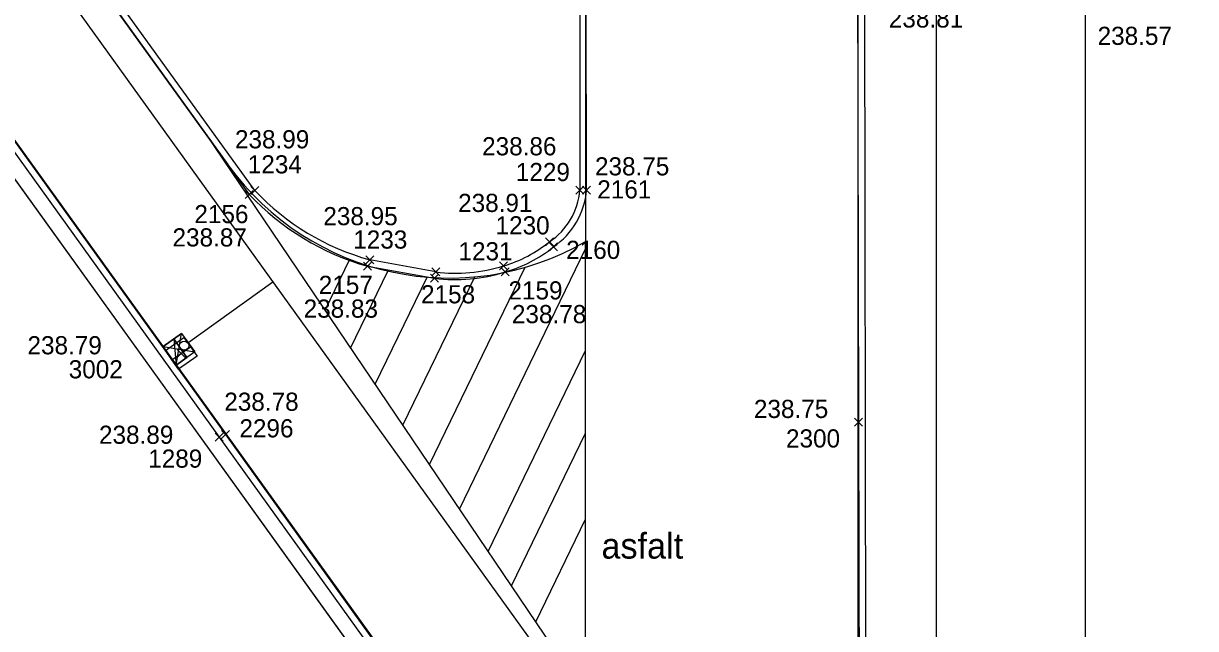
# Model space of a CAD drawing. Extents: x -264222 to -263676, y -1242344 to -1242060.
# Drawn here: x -264143.94 to -264118.14, y -1242285.58 to -1242272.25 of the extents above; entities that cross this region are included whole.
import ezdxf

# ---------------------------------------------------------------- set-up
doc = ezdxf.new("R2010")
doc.units = 0
for name, color, linetype in [('BODY_CISLO', 7, 'Continuous'), ('BODY_SYMBOL', 7, 'Continuous'), ('BODY_VYSKA', 7, 'Continuous'), ('BODY_VYSKY_UV', 7, 'Continuous'), ('KOORDINACNA_SITUACIA_DSP', 7, 'Continuous'), ('POPIS', 7, 'Continuous'), ('PROJEKT_DRS_OBRUBNIKY_KOMUNIKACIE', 7, 'Continuous'), ('PROJEKT_DRS_TDZ_VODOROVNE', 7, 'Continuous'), ('PROJEKT_DRS_UV_STAVBY', 7, 'Continuous'), ('SO_20-3_OBRUBNIKY_DOLNA_HRANA', 7, 'Continuous'), ('SO_20-3_OBRUBNIKY_HORNA_HRANA', 7, 'Continuous'), ('ULICNA_VPUST_POKLOP', 7, 'Continuous')]:
    doc.layers.add(name, color=color, linetype=linetype)

msp = doc.modelspace()

# ---------------------------------------------------------------- linework, layer by layer
at = {"layer": 'BODY_SYMBOL'}
for p, q in [((-264139.06, -1242276.105), (-264138.884, -1242275.929)), ((-264138.884, -1242276.105), (-264139.06, -1242275.929)), ((-264138.939, -1242276.021), (-264138.763, -1242275.845)), ((-264138.763, -1242276.021), (-264138.939, -1242275.845)), ((-264131.781, -1242276.013), (-264131.605, -1242275.837)), ((-264131.605, -1242276.013), (-264131.781, -1242275.837)), ((-264131.636, -1242276.013), (-264131.46, -1242275.837)), ((-264131.46, -1242276.013), (-264131.636, -1242275.837)), ((-264132.453, -1242277.149), (-264132.277, -1242276.973)), ((-264132.277, -1242277.149), (-264132.453, -1242276.973)), ((-264132.363, -1242277.261), (-264132.187, -1242277.085)), ((-264132.187, -1242277.261), (-264132.363, -1242277.085)), ((-264136.408, -1242277.546), (-264136.232, -1242277.37)), ((-264136.232, -1242277.546), (-264136.408, -1242277.37)), ((-264136.454, -1242277.688), (-264136.278, -1242277.512)), ((-264136.278, -1242277.688), (-264136.454, -1242277.512)), ((-264133.463, -1242277.682), (-264133.287, -1242277.506)), ((-264133.287, -1242277.682), (-264133.463, -1242277.506)), ((-264134.979, -1242277.951), (-264134.803, -1242277.775)), ((-264134.803, -1242277.951), (-264134.979, -1242277.775)), ((-264134.953, -1242277.814), (-264134.777, -1242277.638)), ((-264134.777, -1242277.814), (-264134.953, -1242277.638)), ((-264133.427, -1242277.814), (-264133.251, -1242277.638)), ((-264133.251, -1242277.814), (-264133.427, -1242277.638)), ((-264140.556, -1242279.607), (-264140.38, -1242279.431)), ((-264140.38, -1242279.607), (-264140.556, -1242279.431)), ((-264125.649, -1242281.122), (-264125.473, -1242280.946)), ((-264125.473, -1242281.122), (-264125.649, -1242280.946)), ((-264139.584, -1242281.393), (-264139.408, -1242281.217)), ((-264139.408, -1242281.393), (-264139.584, -1242281.217)), ((-264139.719, -1242281.449), (-264139.543, -1242281.273)), ((-264139.543, -1242281.449), (-264139.719, -1242281.273))]:
    msp.add_line(p, q, dxfattribs=at)
at = {"layer": 'KOORDINACNA_SITUACIA_DSP'}
for p, q in [((-264204.694, -1242191.482), (-264122.859, -1242305.266)), ((-264204.078, -1242191.482), (-264122.243, -1242305.266)), ((-264123.854, -1242237.976), (-264123.854, -1242297.736)), ((-264153.916, -1242255.234), (-264139.439, -1242275.363)), ((-264152.757, -1242258.05), (-264124.146, -1242297.83)), ((-264152.757, -1242258.05), (-264124.146, -1242297.83)), ((-264131.568, -1242270.982), (-264131.568, -1242277.056)), ((-264125.568, -1242287.467), (-264125.568, -1242270.982)), ((-264140.324, -1242279.287), (-264138.451, -1242277.94)), ((-264140.868, -1242279.37), (-264140.632, -1242279.201)), ((-264140.576, -1242279.776), (-264140.868, -1242279.37)), ((-264140.632, -1242279.201), (-264140.341, -1242279.607)), ((-264140.632, -1242279.201), (-264140.576, -1242279.776)), ((-264140.632, -1242279.201), (-264140.576, -1242279.776)), ((-264140.341, -1242279.607), (-264140.632, -1242279.201)), ((-264140.341, -1242279.607), (-264140.576, -1242279.776)), ((-264140.576, -1242279.776), (-264140.341, -1242279.607))]:
    msp.add_line(p, q, dxfattribs=at)
for points in [[(-264204.694, -1242191.482), (-264137.78, -1242284.52), (-264125.581, -1242301.482)], [(-264120.568, -1242296.035), (-264120.568, -1242271.189), (-264120.568, -1242271.189)]]:
    msp.add_lwpolyline(points, dxfattribs=at)
msp.add_circle((-264140.403, -1242279.349), 0.1, dxfattribs=at)
msp.add_arc((-264134.568, -1242271.86), 6, 215.724, 300, dxfattribs=at)
at = {"layer": 'PROJEKT_DRS_OBRUBNIKY_KOMUNIKACIE'}
for p, q in [((-264204.694, -1242191.482), (-264115.871, -1242314.982)), ((-264204.078, -1242191.482), (-264119.571, -1242308.982)), ((-264153.916, -1242255.234), (-264139.439, -1242275.363)), ((-264131.568, -1242270.982), (-264131.568, -1242277.056)), ((-264125.568, -1242287.467), (-264125.568, -1242270.982)), ((-264120.568, -1242296.035), (-264120.568, -1242271.189))]:
    msp.add_line(p, q, dxfattribs=at)
msp.add_lwpolyline([(-264204.694, -1242191.482), (-264137.78, -1242284.52), (-264125.581, -1242301.482)], dxfattribs=at)
msp.add_arc((-264134.568, -1242271.86), 6, 215.724, 300, dxfattribs=at)
at = {"layer": 'PROJEKT_DRS_TDZ_VODOROVNE'}
for p, q in [((-264134.346, -1242282.947), (-264131.568, -1242277.22)), ((-264137.302, -1242278.57), (-264136.756, -1242277.446)), ((-264135.007, -1242281.969), (-264132.898, -1242277.623)), ((-264136.741, -1242279.401), (-264135.918, -1242277.706)), ((-264136.202, -1242280.199), (-264135.057, -1242277.84)), ((-264135.592, -1242281.102), (-264134.007, -1242277.833)), ((-264133.714, -1242283.883), (-264131.568, -1242279.459)), ((-264133.202, -1242284.642), (-264131.568, -1242281.274)), ((-264132.667, -1242285.434), (-264131.568, -1242283.169))]:
    msp.add_line(p, q, dxfattribs=at)
msp.add_lwpolyline([(-264139.918, -1242274.696), (-264131.568, -1242287.061), (-264131.568, -1242277.056)], dxfattribs=at)
at = {"layer": 'PROJEKT_DRS_UV_STAVBY'}
msp.add_lwpolyline([(-264140.576, -1242279.776), (-264140.868, -1242279.37), (-264140.462, -1242279.078), (-264140.17, -1242279.484), (-264140.576, -1242279.776), (-264140.462, -1242279.078), (-264140.868, -1242279.37), (-264140.17, -1242279.484)], dxfattribs=at)
at = {"layer": 'SO_20-3_OBRUBNIKY_DOLNA_HRANA'}
for p, q in [((-264131.548, -1242275.925), (-264131.555, -1242270.935)), ((-264136.366, -1242277.6), (-264134.891, -1242277.863))]:
    msp.add_line(p, q, dxfattribs=at)
for points in [[(-264179.08, -1242196.474), (-264200.47, -1242196.472), (-264195.765, -1242203.023), (-264189.923, -1242211.168), (-264184.11, -1242219.268), (-264178.281, -1242227.391), (-264171.252, -1242237.149), (-264164.83, -1242246.079), (-264158.406, -1242254.997), (-264151.981, -1242263.929), (-264145.549, -1242272.885), (-264139.496, -1242281.305), (-264132.148, -1242291.541), (-264125.165, -1242301.265), (-264124.808, -1242301.762)], [(-264154.16, -1242254.916), (-264146.578, -1242265.475), (-264138.972, -1242276.017)], [(-264125.585, -1242271.017), (-264125.561, -1242281.034), (-264125.551, -1242287.051)]]:
    msp.add_lwpolyline(points, dxfattribs=at)
for centre, major_axis, ratio, start_param, end_param in [((-264134.793, -1242272.072), (1.661, -5.503), 0.999756, 5.175839, 5.71277), ((-264133.222, -1242275.788), (1.449, 0.851), 0.998406, 4.780647, 5.669539), ((-264134.142, -1242274.881), (2.533, 1.525), 0.999647, 4.445425, 4.853802), ((-264134.422, -1242274.319), (0.823, -3.479), 0.999728, 5.919135, 6.358584)]:
    msp.add_ellipse(centre, major_axis=major_axis, ratio=ratio, start_param=start_param, end_param=end_param, dxfattribs=at)
at = {"layer": 'SO_20-3_OBRUBNIKY_HORNA_HRANA'}
for p, q in [((-264131.7, -1242270.94), (-264131.693, -1242275.925)), ((-264125.435, -1242271.03), (-264125.41, -1242287.033)), ((-264134.865, -1242277.726), (-264136.32, -1242277.458))]:
    msp.add_line(p, q, dxfattribs=at)
for points in [[(-264204.226, -1242191.388), (-264204.22, -1242191.499), (-264200.55, -1242196.62), (-264195.884, -1242203.112), (-264190.046, -1242211.249), (-264184.226, -1242219.352), (-264178.398, -1242227.475), (-264171.378, -1242237.231), (-264164.951, -1242246.159), (-264158.525, -1242255.075), (-264152.106, -1242264.005), (-264145.671, -1242272.964), (-264139.631, -1242281.361), (-264132.272, -1242291.613), (-264125.285, -1242301.347), (-264124.926, -1242301.846)], [(-264138.851, -1242275.933), (-264146.457, -1242265.393), (-264154.039, -1242254.835)]]:
    msp.add_lwpolyline(points, dxfattribs=at)
for centre, major_axis, ratio, start_param, end_param in [((-264134.867, -1242272.183), (-0.221, -5.466), 0.999887, 5.50793, 6.054882), ((-264133.2, -1242275.804), (1.245, 0.861), 0.996982, 4.693871, 5.596569), ((-264134.185, -1242274.837), (2.588, 1.292), 0.993304, 4.536396, 4.933863), ((-264134.431, -1242274.144), (-0.647, -3.55), 0.999738, 0.059669, 0.477357)]:
    msp.add_ellipse(centre, major_axis=major_axis, ratio=ratio, start_param=start_param, end_param=end_param, dxfattribs=at)
at = {"layer": 'ULICNA_VPUST_POKLOP'}
msp.add_line((-264140.468, -1242279.519), (-264140.468, -1242279.519), dxfattribs=at)
msp.add_lwpolyline([(-264140.673, -1242279.662), (-264140.816, -1242279.458), (-264140.407, -1242279.171), (-264140.12, -1242279.58), (-264140.529, -1242279.867), (-264140.673, -1242279.662), (-264140.263, -1242279.376)], dxfattribs=at)

# ---------------------------------------------------------------- texts
at = {"layer": 'BODY_CISLO'}
for s, p in [('1234', (-264139.003, -1242275.556)), ('1229', (-264133.104, -1242275.725)), ('2161', (-264131.312, -1242276.108)), ('2156', (-264140.178, -1242276.651)), ('1230', (-264133.55, -1242276.899)), ('1233', (-264136.682, -1242277.212)), ('1231', (-264134.366, -1242277.47)), ('2160', (-264131.996, -1242277.439)), ('2157', (-264137.441, -1242278.21)), ('2158', (-264135.19, -1242278.417)), ('2159', (-264133.266, -1242278.332)), ('3002', (-264142.944, -1242280.069)), ('2296', (-264139.187, -1242281.369)), ('2300', (-264127.158, -1242281.592)), ('1289', (-264141.194, -1242282.036))]:
    msp.add_text(s, height=0.4, dxfattribs=at).set_placement(p)
at = {"layer": 'BODY_VYSKA'}
for s, p in [('238.81', (-264124.895, -1242272.344)), ('238.57', (-264120.3, -1242272.726)), ('238.99', (-264139.285, -1242275.004)), ('238.86', (-264133.846, -1242275.158)), ('238.75', (-264131.362, -1242275.6)), ('238.91', (-264134.374, -1242276.405)), ('238.95', (-264137.34, -1242276.697)), ('238.87', (-264140.659, -1242277.165)), ('238.83', (-264137.773, -1242278.733)), ('238.78', (-264133.19, -1242278.854)), ('238.78', (-264139.52, -1242280.783)), ('238.75', (-264127.864, -1242280.942)), ('238.89', (-264142.277, -1242281.511))]:
    msp.add_text(s, height=0.4, dxfattribs=at).set_placement(p)
at = {"layer": 'BODY_VYSKY_UV'}
msp.add_text('238.79', height=0.4, dxfattribs=at).set_placement((-264143.851, -1242279.54))
at = {"layer": 'POPIS'}
msp.add_text('asfalt', height=0.5625, dxfattribs=at).set_placement((-264131.219, -1242284.039))

doc.saveas('drawing.dxf')
